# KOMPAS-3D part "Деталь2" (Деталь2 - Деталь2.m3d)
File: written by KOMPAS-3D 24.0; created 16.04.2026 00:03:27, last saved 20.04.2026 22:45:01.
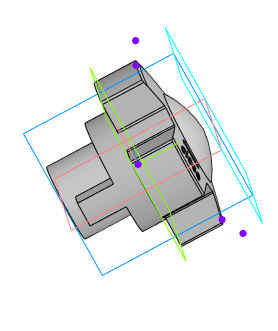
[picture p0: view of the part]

Document properties: Автор: tyuri; Полное имя файла: C:\Работа\VB0000P-T DN X PN 25 Клапан балансировочный DN.ru\DN25\исходные материалы\Деталь2 - Деталь2.m3d

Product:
- Body: Твердое тело1  | qty 1
    Масса: 0.240364
- Part/product: Деталь2
    Масса: 0.240364
    additional columns: Типовые

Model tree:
1. Твердое тело1  (labels: Твердое тело1)
2. Смещенная плоскость:1
     Расстояние = 25
3. Эскиз:2
4. Элемент вращения:1
     Угол 1 = 360
5. Эскиз:3  (with: Ребро.Элемент вращения:1)  (labels: Грань.Твердое тело1; Ребро.Твердое тело1)
6. Элемент вращения:2
     Угол 1 = 360
7. Эскиз:4  (with: Ребро.Элемент вращения:1)  (labels: Грань.Твердое тело1)
8. Элемент выдавливания:2  (with: Грань.Элемент вращения:1)
     Расстояние 1 = 0.481617
9. Эскиз:5  (with: Ребро.Элемент вращения:1)
10. Элемент вращения:3
     Угол 1 = 360
11. Эскиз:12  (labels: Грань.Твердое тело1; Ребро.Твердое тело1)
12. Элемент выдавливания:4  (labels: Грань.Твердое тело1)
     Расстояние 2 = 10
13. Эскиз:14  (with: Грань.Элемент выдавливания:4)
14. Элемент выдавливания:5
     Расстояние 1 = 20
15. Эскиз:15  (with: Грань.Элемент выдавливания:4, Ребро.Элемент выдавливания:5)  (labels: Ребро.Твердое тело1)
16. Элемент выдавливания:6
     Расстояние 1 = 15
17. Эскиз:16
18. Эскиз:17
19. Элемент выдавливания:7  (with: Грань.Элемент вращения:1)
     Расстояние 1 = 23.9129; Смещение 1 = 0.1
20. Точка:1  (with: Ребро.Элемент вращения:1)
     X = 34; Y = 17.077; Смещение (% от длины кривой) = 50
21. Точка:2  (with: Ребро.Элемент вращения:1)
     X = -34; Y = 17.077; Смещение (% от длины кривой) = 50
22. Масштабирование:1
23. Масштабирование : Твердое тело1  (labels: Масштабирование : Точка:1; Масштабирование : Точка:2)
     Масштаб по оси Х = 1; Масштаб по оси Y = 1; Масштаб по оси Z = 1; Коэффициент = 0.8

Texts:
  GOST 26.020 Pr3
  Масштабирование : Вершина.Начало координат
